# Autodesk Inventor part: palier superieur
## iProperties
Created: 2001-10
Part Number: palier superieur
Material: Par défaut
Document SubType Name: Modélisation
Designer: User
Control State: 0
Master: False
Checked Out: False
Shininess: 20.0
Length Units: 11269
Angle Units: 11279
Time Units: 11290
Mass Units: 11283
Length Display Precision: 3
Angle Display Precision: 2
Density: 0.0
Volumn: 0.0
Area: 0.0
PropertySet Name: Model Information
Author: User
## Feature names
1. Révolution1 [Revolution]
2. Extrusion1
3. Chanfrein1 [Chamfer]
4. Extrusion2
